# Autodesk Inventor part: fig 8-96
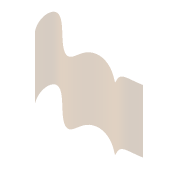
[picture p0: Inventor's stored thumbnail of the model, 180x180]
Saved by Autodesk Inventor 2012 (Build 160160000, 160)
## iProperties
Shininess: 64.0
Length Units: 11269
Angle Units: 11279
Time Units: 11290
Mass Units: 11283
Length Display Precision: 3
Angle Display Precision: 2
Compacted: True
Part Number: fig 8-96
Document SubType Name: Modeling
Created: 2003-08
Designer: Owner
Manufacturer: Standard
Standards Organization: Custom
Density: 1 g/cm^3
Material: Default
Density: 0.0
Volumn: 0.0
Area: 0.0
PropertySet Name: Model Information
Control State: 0
Master: False
Checked Out: False
Author: Owner
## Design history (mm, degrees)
sketch "Sketch1"
  geometry: 7 further points
  constraints: 7 other
  dimensions: "d0" = 80 horizontal distance of point (40, 1.742) point (-40, -4.065); "d1" = 40 horizontal distance of point (0, 0) point (-40, -4.065)
extrude_surface "ExtrusionSrf1" sketch "Sketch1" dims "d2" = 80, "d3" = 0
sketch "Sketch2"
  geometry: L1 (40, 0)-(40, -40) reference; L2 (-40, 0)-(-40, -40) reference; 7 further points
  constraints: 2 point on line, 7 other
extrude_surface "ExtrusionSrf2" dims "d4" = 80, "d5" = 0
split "Split6"
sketch "3D Sketch1"
feature "SweepSrf1" sketch "3D Sketch1" dims "d6" = 0
feature "Extend1" dims "d7" = 10
body "Srf1"
body "Srf2"
body "Srf3"
node "3D Intersection1"
